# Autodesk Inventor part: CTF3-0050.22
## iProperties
Shininess: 64.0
Length Units: 11269
Angle Units: 11279
Time Units: 11290
Mass Units: 11283
Length Display Precision: 3
Angle Display Precision: 2
Compacted: True
Part Number: CTF3-0050.22
Document SubType Name: Modeling
Created: 2004-02
Designer: lollo
Density: 0.0
Volumn: 0.0
Area: 0.0
PropertySet Name: Model Information
Control State: 0
Master: False
Checked Out: False
Author: lollo
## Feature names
1. Estrusione1 [Extrusion]
2. Foro1 [Hole]
3. Smusso1 [Chamfer]
4. Foro2 [Hole]
5. Raccordo1 [Fillet]
